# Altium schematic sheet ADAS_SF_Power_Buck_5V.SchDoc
size 431 x 279 mm; Date: Not shown in title block; ApprovedBy: Not shown in title block; CheckedBy: Not shown in title block; Author: Not shown in title block; CompanyName: Not shown in title block; Engineer: Not shown in title block; Organization: Not shown in title block; Address1: Not shown in title block; Address2: Not shown in title block; Address3: Not shown in title block; Address4: Not shown in title block; DocumentNumber: 1; Revision: Use project parameter SCH_Rev; SheetNumber: 3; SheetTotal: 15; PageSetup: Record=PageOptions¦CenterHorizontal=True¦CenterVertical=True¦PrintScale=0.66¦XCorrection=1.00¦YCorrection=1.00¦PrintKind=0¦BorderSize=5000000¦LeftOffset=0¦BottomOffset=0¦Orientation=2¦PaperLength=1000¦PaperWidth=1000¦Scale=100¦PaperSource=15¦PrintQuality=600¦MediaType=1¦DitherType=10¦PrintScaleMode=1¦PaperKind=Letter
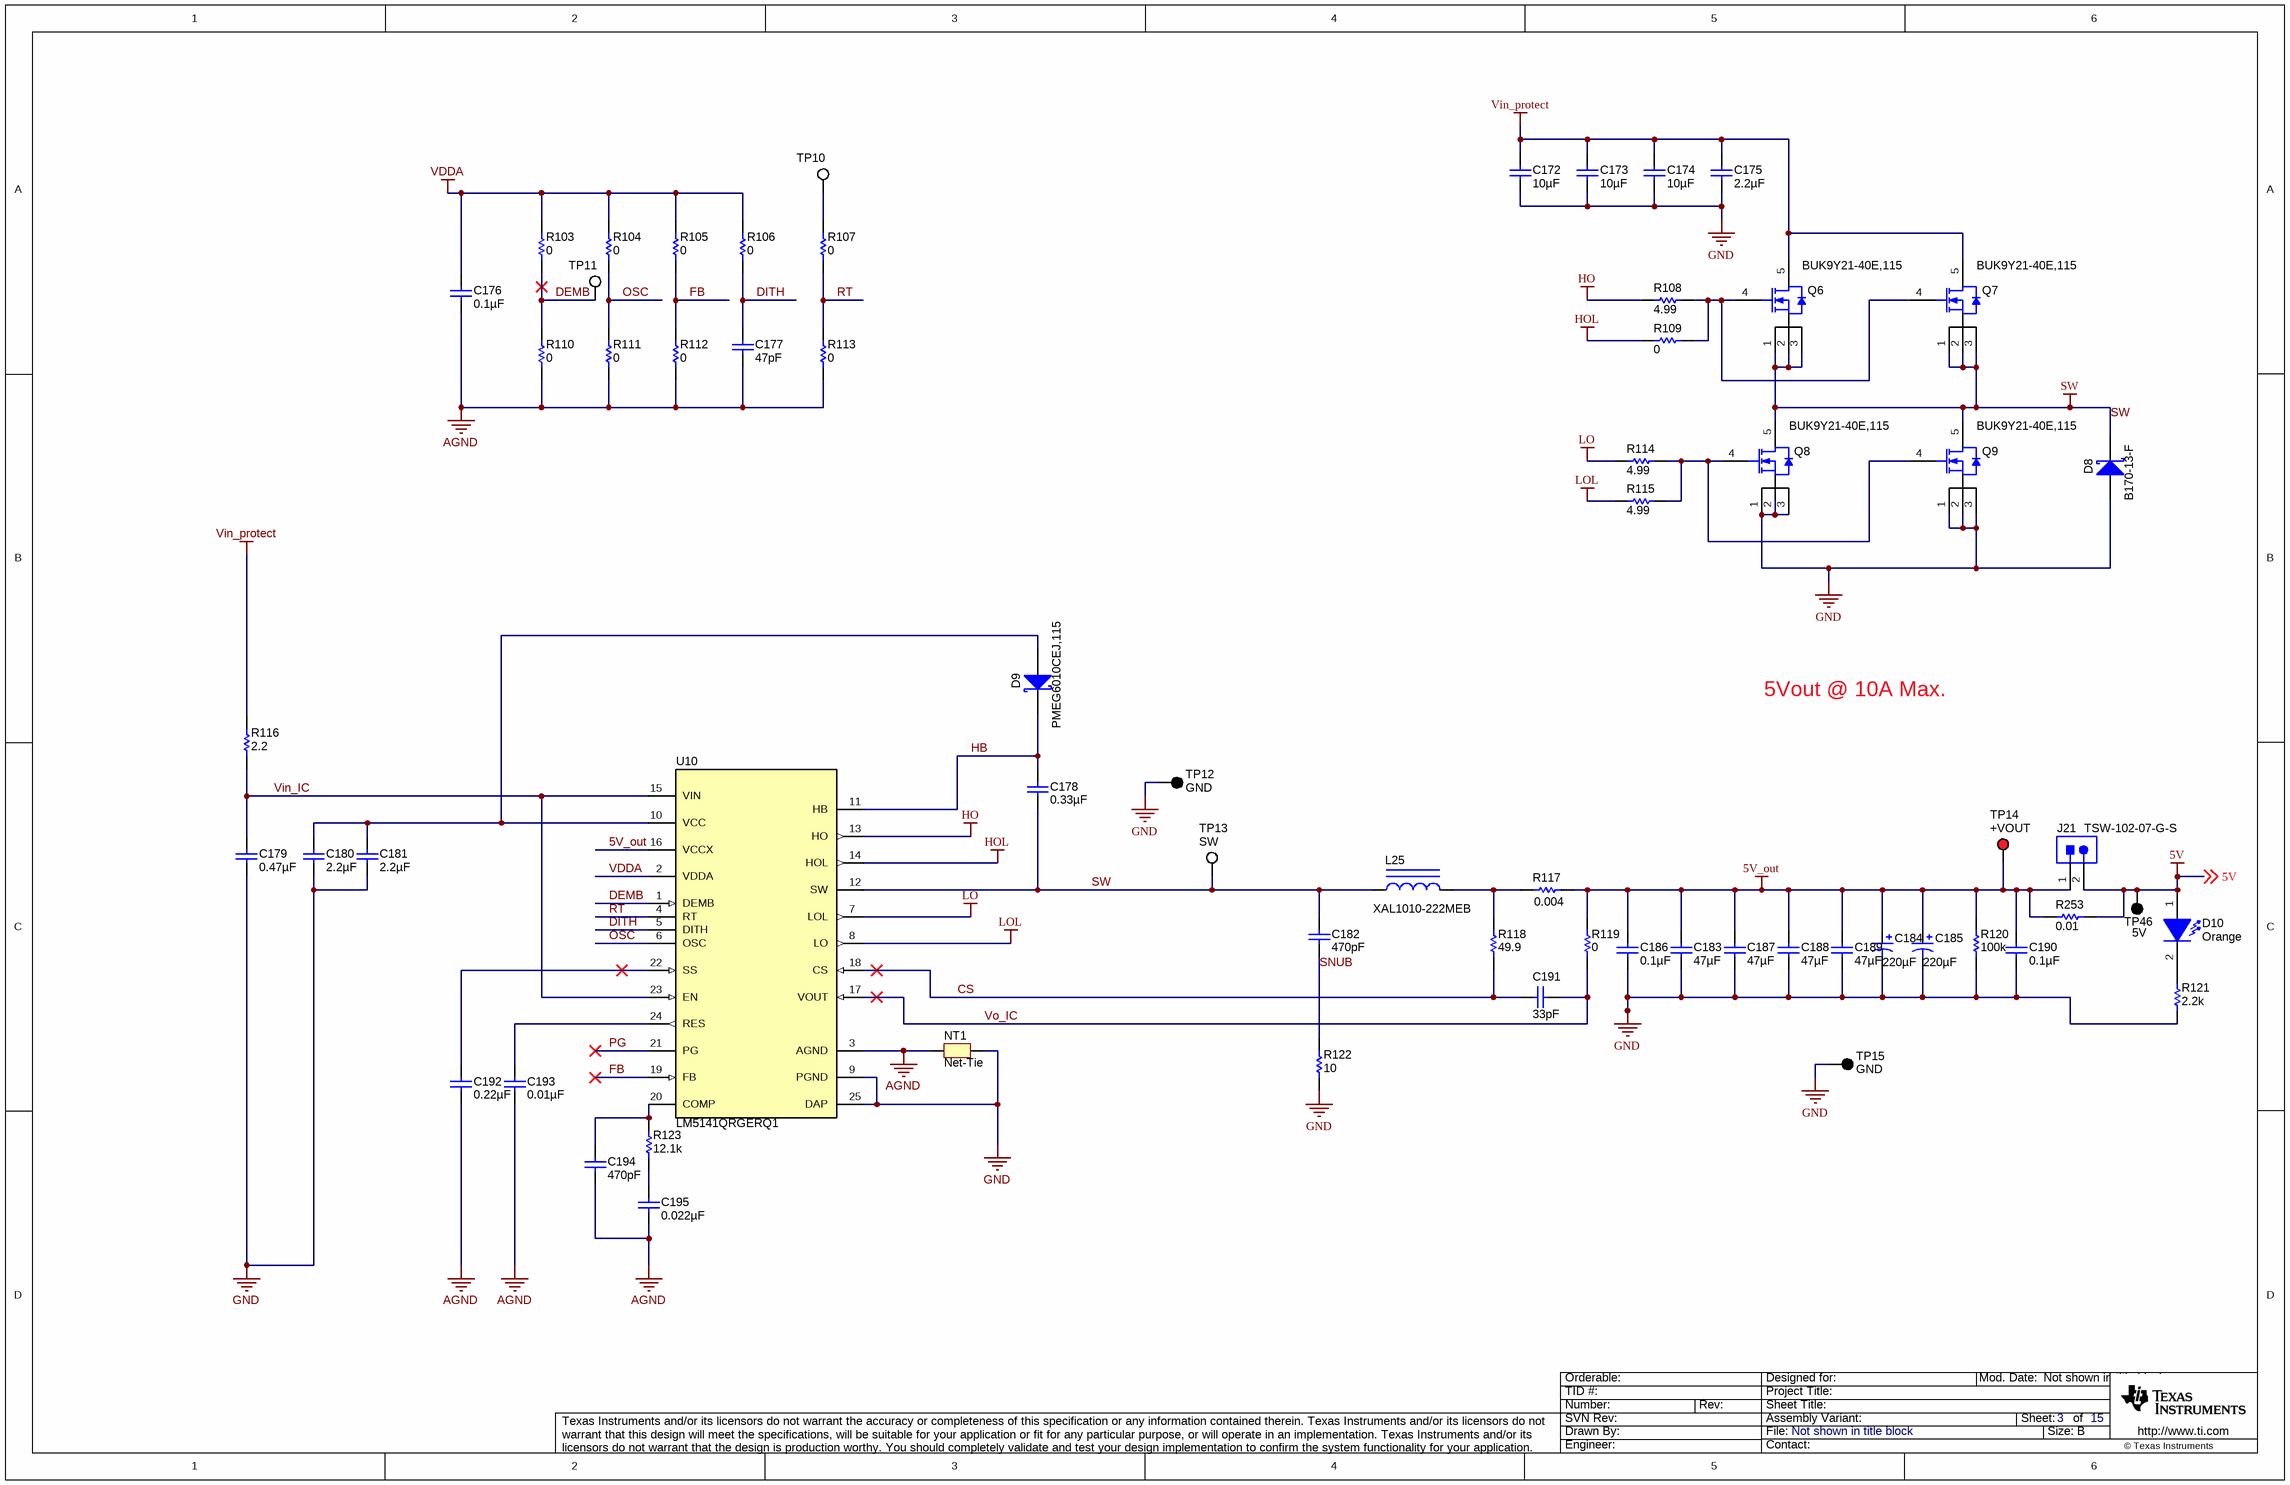
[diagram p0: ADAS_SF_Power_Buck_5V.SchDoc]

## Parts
C172  ValueDisplayed: 10µF  [1206_190]  (hidden comment: CGA5L3X5R1H106K160AB)
C173  ValueDisplayed: 10µF  [1206_190]  (hidden comment: CGA5L3X5R1H106K160AB)
C174  ValueDisplayed: 10µF  [1206_190]  (hidden comment: CGA5L3X5R1H106K160AB)
C175  2.2µF  [1206]
C176  ValueDisplayed: 0.1µF  [0402]  (hidden comment: GCM155R71H104KE02D)
C177  ValueDisplayed: 47pF  [0402]  (hidden comment: GRM1555C1E470JA01D)
C178  ValueDisplayed: 0.33µF  [0805_HV]  (hidden comment: GRM21AR72A334KAC5L)
C179  ValueDisplayed: 0.47µF  [0805_HV]  (hidden comment: GRM21BR72A474KA73L)
C180  ValueDisplayed: 2.2µF  [0603_HV]  (hidden comment: C0603C225M8PACTU)
C181  ValueDisplayed: 2.2µF  [0603_HV]  (hidden comment: C0603C225M8PACTU)
C182  ValueDisplayed: 470pF  [0805_HV]  (hidden comment: 08051A471JAT2A)
C183  ValueDisplayed: 47µF  [1206_180]  (hidden comment: GRM31CR61A476KE15L)
C184  ValueDisplayed: 220µF  [CAPSMT_62_H70]  (hidden comment: APXA6R3ARA221MH70G)
C185  ValueDisplayed: 220µF  [CAPSMT_62_H70]  (hidden comment: APXA6R3ARA221MH70G)
C186  ValueDisplayed: 0.1µF  [0603L]  (hidden comment: GRM188R72A104KA35D)
C187  ValueDisplayed: 47µF  [1206_180]  (hidden comment: GRM31CR61A476KE15L)
C188  ValueDisplayed: 47µF  [1206_180]  (hidden comment: GRM31CR61A476KE15L)
C189  ValueDisplayed: 47µF  [1206_180]  (hidden comment: GRM31CR61A476KE15L)
C190  ValueDisplayed: 0.1µF  [0603L]  (hidden comment: GRM188R72A104KA35D)
C191  ValueDisplayed: 33pF  [0603L]  (hidden comment: 06031A330JAT2A)
C192  ValueDisplayed: 0.22µF  [0402]  (hidden comment: GRM155R61A224KE19D)
C193  ValueDisplayed: 0.01µF  [0402]  (hidden comment: GCM155R71H103KA55D)
C194  ValueDisplayed: 470pF  [0402]  (hidden comment: GRM1555C1E471JA01D)
C195  ValueDisplayed: 0.022µF  [0402]  (hidden comment: GRM155R71C223KA01D)
D8  B170-13-F  [SMA]
D9  PMEG6010CEJ,115  [SOD-323F]
D10  value Orange  [LED_SMLP12_ORANGE]  (hidden comment: SML-P12DTT86)
J21  TSW-102-07-G-S  [TSW-102-07-G-S]
L25  XAL1010-222MEB  [XAL1010]
NT1  Net-Tie  [Net-Tie_10mil]  (net tie, no BOM)
Q6  BUK9Y21-40E,115  [LFPAK56]
Q7  BUK9Y21-40E,115  [LFPAK56]
Q8  BUK9Y21-40E,115  [LFPAK56]
Q9  BUK9Y21-40E,115  [LFPAK56]
R103  ValueDisplayed: 0  [0402]  (hidden comment: CRCW04020000Z0ED)
R104  ValueDisplayed: 0  [0402]  (hidden comment: CRCW04020000Z0ED)
R105  ValueDisplayed: 0  [0402]  (hidden comment: CRCW04020000Z0ED)
R106  ValueDisplayed: 0  [0402]  (hidden comment: CRCW04020000Z0ED)
R107  ValueDisplayed: 0  [0402]  (hidden comment: CRCW04020000Z0ED)
R108  ValueDisplayed: 4.99  [0603L]  (hidden comment: CRCW06034R99FKEA)
R109  ValueDisplayed: 0  [0603L]  (hidden comment: CRCW06030000Z0EA)
R110  ValueDisplayed: 0  [0402]  (hidden comment: CRCW04020000Z0ED)
R111  ValueDisplayed: 0  [0402]  (hidden comment: CRCW04020000Z0ED)
R112  ValueDisplayed: 0  [0402]  (hidden comment: CRCW04020000Z0ED)
R113  ValueDisplayed: 0  [0402]  (hidden comment: CRCW04020000Z0ED)
R114  ValueDisplayed: 4.99  [0603L]  (hidden comment: CRCW06034R99FKEA)
R115  ValueDisplayed: 4.99  [0603L]  (hidden comment: CRCW06034R99FKEA)
R116  ValueDisplayed: 2.2  [0603L]  (hidden comment: CRCW06032R20JNEA)
R117  value 0.004  [2010]  (hidden comment: PMR50HZPFV4L00)
R118  ValueDisplayed: 49.9  [0603L]  (hidden comment: CRCW060349R9FKEA)
R119  ValueDisplayed: 0  [0603L]  (hidden comment: CRCW06030000Z0EA)
R120  ValueDisplayed: 100k  [0805_HV]  (hidden comment: CRCW0805100KFKEA)
R121  ValueDisplayed: 2.2k  [0402]  (hidden comment: CRCW04022K20JNED)
R122  ValueDisplayed: 10  [2010]  (hidden comment: CRCW201010R0JNEF)
R123  ValueDisplayed: 12.1k  [0402]  (hidden comment: CRCW040212K1FKED)
R253  ValueDisplayed: 0.01  [KRL2012]  (hidden comment: KRL2012E-M-R010-F-T5)
TP10  5012  [Keystone5012]  (value not drawn)
TP11  5012  [Keystone5012]  (value not drawn)
TP12  GND  [Keystone5011]
TP13  SW  [Keystone5012]
TP14  +VOUT  [Keystone5010]
TP15  GND  [Keystone5011]
TP46  5V  [Keystone5011]
U10  LM5141QRGERQ1  [RGE0024J_NV]

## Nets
5V: D10.1(A) J21.2 R253.2 TP46.1 ; off-sheet 5V
5V_out: C183.1 C184.1(+) C185.1(+) C186.2 C187.1 C188.1 C189.1 C190.2 J21.1 R117.2 R119.2 R120.2 R253.1 TP14.1 U10.16(VCCX)
AGND: C176.2 C177.1 C192.2 C193.2 C194.1 C195.2 NT1.2 R110.1 R111.1 R112.1 R113.1 U10.3(AGND)
GND: C172.2 C173.2 C174.2 C175.2 C179.1 C180.2 C181.1 C183.2 C184.2(-) C185.2(-) C186.1 C187.2 C188.2 C189.2 C190.1 D8.2(A) NT1.1 Q8.1(S) Q8.2(S) Q8.3(S) Q9.1(S) Q9.2(S) Q9.3(S) R120.1 R121.2 R122.1 TP12.1 TP15.1 U10.9(PGND) U10.25(DAP)
HO: R108.1 U10.13(HO)
HOL: R109.1 U10.14(HOL)
LO: R114.1 U10.7(LOL)
LOL: R115.1 U10.8(LO)
SW: C178.1 C182.2 D8.1(K) L25.1 Q6.1(S) Q6.2(S) Q6.3(S) Q7.1(S) Q7.2(S) Q7.3(S) Q8.5(D) Q9.5(D) TP13.1 U10.12(SW)
VDDA: C176.1 R103.2 R104.2 R105.2 R106.2 U10.2(VDDA)
Vin_protect: C172.1 C173.1 C174.1 C175.1 Q6.5(D) Q7.5(D) R116.2
CS: C191.2 R118.1 U10.18(CS)
DEMB: R103.1 R110.2 TP11.1 U10.1(DEMB)
DITH: C177.2 R106.1 U10.5(DITH)
FB: R105.1 R112.2 U10.19(FB)
HB: C178.2 D9.1(K) U10.11(HB)
OSC: R104.1 R111.2 U10.6(OSC)
PG: U10.21(PG)
RT: R107.1 R113.2 U10.4(RT)
SNUB: C182.1 R122.2
Vin_IC: C179.2 R116.1 U10.15(VIN) U10.23(EN)
Vo_IC: C191.1 R119.1 U10.17(VOUT)
NetC180_1: C180.1 C181.2 D9.2(A) U10.10(VCC)
NetC192_1: C192.1 U10.22(SS)
NetC193_1: C193.1 U10.24(RES)
NetC194_2: C194.2 R123.2 U10.20(COMP)
NetC195_1: C195.1 R123.1
NetD10_2: D10.2(K) R121.1
NetL25_2: L25.2 R117.1 R118.2
NetQ6_4: Q6.4(G) Q7.4(G) R108.2 R109.2
NetQ8_4: Q8.4(G) Q9.4(G) R114.2 R115.2
NetR107_2: R107.2 TP10.1

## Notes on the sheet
- 5Vout @ 10A Max.

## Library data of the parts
C172-C174 = CGA5L3X5R1H106K160AB: CAP, CERM, 10 µF, 50 V, +/- 10%, X5R, 1206_190; Manufacturer: TDK; Polarized: N; CompType: Capacitor; Value: 10uF; U/M: EA; Cap_F: 0.00001; Tolerance_%: 10; Value1: Unknown; VDC_V: 50; Value2: 50V; TaMin_C: -55; TaMax_C: 85; Cap_Case: 1206
C175 = CL31B225KCHSNNE: CAP CER 2.2UF 100V 10% X7R 1206; Manufacturer: Samsung Electro-Mechanics America, Inc; SymbolVersion: use current date i.e. 2008-05-20; SymbolCreator: Use a-id; CompType: Used in some BOM reports.  Useful for finding later.; U/M: EA, IN, or GM
C176 = GCM155R71H104KE02D: CAP, CERM, 0.1 µF, 50 V, +/- 10%, X7R, AEC-Q200 Grade 1, 0402; Manufacturer: MuRata; Polarized: N; CompType: Capacitor; Value: 0.1uF; U/M: EA; Cap_F: 0.0000001; Tolerance_%: 10; Value1: Unknown; VDC_V: 50; Value2: 50V; TaMin_C: -55; TaMax_C: 125; AEC Category: Q200; AEC Qualified: Y; AEC Grade: 1; SizeArea_mm2: 0.5; SizeAreaWB_mm2: 3; SizeZ_mm: 0.6
C177 = GRM1555C1E470JA01D: CAP, CERM, 47 pF, 25 V, +/- 5%, C0G/NP0, 0402; Manufacturer: MuRata; Polarized: N; CompType: Capacitor; Value: 47pF; U/M: EA; Cap_F: 0.000000000047; Tolerance_%: 5; Value1: Unknown; VDC_V: 25; Value2: 25V; TaMin_C: -55; TaMax_C: 125; AEC Category: Q200
C178 = GRM21AR72A334KAC5L: CAP, CERM, 0.33 µF, 100 V, +/- 10%, X7R, 0805; Manufacturer: MuRata; Polarized: N; CompType: Capacitor; Value: 0.33uF; U/M: EA; Cap_F: 0.00000033; Tolerance_%: 10; Value1: Unknown; VDC_V: 100; Value2: 100V; TaMin_C: -55; TaMax_C: 125; Cap_Case: 0805
C179 = GRM21BR72A474KA73L: CAP, CERM, 0.47uF, 100V, +/-10%, X7R, 0805; Manufacturer: MuRata; Polarized: N; CompType: Capacitor; U/M: EA; Cap_F: 0.00000047; Tolerance_%: 10; Value1: Unknown; VDC_V: 100; TaMin_C: -55; TaMax_C: 125; Cap_Case: 0805
C180 C181 = C0603C225M8PACTU: CAP, CERM, 2.2 µF, 10 V, +/- 20%, X5R, 0603; Manufacturer: Kemet; Polarized: N; CompType: Capacitor; Value: 2.2uF; U/M: EA; Cap_F: 0.0000022; Tolerance_%: 20; Value1: Unknown; VDC_V: 10; Value2: 10V; TaMin_C: -55; TaMax_C: 85; Cap_Case: 0603
C182 = 08051A471JAT2A: CAP, CERM, 470 pF, 100 V, +/- 5%, C0G/NP0, 0805; Manufacturer: AVX; Polarized: N; CompType: Capacitor; Value: 470pF; U/M: EA; Cap_F: 0.00000000047; Tolerance_%: 5; ESR_ohm: 0.159; Value1: 0.159 ohm; VDC_V: 100; Value2: 100V; TaMin_C: -55; TaMax_C: 125; Cap_Case: 0805; SizeArea_mm2: 2.5; SizeAreaWB_mm2: 6.75; SizeX_mm: 2; SizeY_mm: 1.25; SizeZ_mm: 1.45; AEC Category: Q200
C183 C187-C189 = GRM31CR61A476KE15L: CAP, CERM, 47 µF, 10 V, +/- 10%, X5R, 1206; Manufacturer: MuRata; Polarized: N; CompType: Capacitor; Value: 47uF; U/M: EA; Cap_F: 0.000047; Tolerance_%: 10; Value1: Unknown; Value2: 10V; TaMin_C: -55; TaMax_C: 85; Cap_Case: 1206; SizeArea_mm2: 5.12; SizeAreaWB_mm2: 10.92; SizeX_mm: 3.2; SizeY_mm: 1.6; SizeZ_mm: 1.8; AEC Category: Q200
C184 C185 = APXA6R3ARA221MH70G: CAP, AL, 220 µF, 6.3 V, +/- 20%, 0.025 ohm, SMD; Manufacturer: Chemi-Con; Polarized: Y; CompType: Capacitor; Value: 220uF; U/M: EA; Cap_F: 0.00022; Tolerance_%: 20; VDC_V: 6.3; Value2: 6.3V; ESR_ohm: 0.025; IRMS_A: 3.02; TaMin_C: -55; TaMax_C: 105; Cap_Case: H70
C186 C190 = GRM188R72A104KA35D: CAP, CERM, 0.1uF, 100V, +/-10%, X7R, 0603; Manufacturer: MuRata; Polarized: N; CompType: Capacitor; U/M: EA; Cap_F: 0.0000001; Tolerance_%: 10; Value1: Unknown; VDC_V: 100; TaMin_C: -55; TaMax_C: 125; Cap_Case: 0603
C191 = 06031A330JAT2A: CAP, CERM, 33 pF, 100 V, +/- 5%, C0G/NP0, 0603; Manufacturer: AVX; Polarized: N; CompType: Capacitor; Value: 33pF; U/M: EA; Cap_F: 0.000000000033; Tolerance_%: 5; ESR_ohm: 0.209; Value1: 0.209 ohm; VDC_V: 100; Value2: 100V; TaMin_C: -55; TaMax_C: 125; Cap_Case: 0603
C192 = GRM155R61A224KE19D: CAP, CERM, 0.22 µF, 10 V, +/- 10%, X5R, 0402; Manufacturer: MuRata; Polarized: N; CompType: Capacitor; Value: 0.22uF; U/M: EA; Cap_F: 0.00000022; Tolerance_%: 10; Value1: Unknown; Value2: 10V; TaMin_C: -55; TaMax_C: 85; SizeArea_mm2: 0.5; SizeAreaWB_mm2: 3; SizeX_mm: 1; SizeZ_mm: 0.6; AEC Category: Q200
C193 = GCM155R71H103KA55D: CAP, CERM, 0.01uF, 50V, +/-10%, C0G/NP0, 0402; Manufacturer: MuRata; Polarized: N; CompType: Capacitor; U/M: EA; Cap_F: 0.00000001; Tolerance_%: 10; Value1: Unknown; VDC_V: 50; TaMin_C: -55; TaMax_C: 125
C194 = GRM1555C1E471JA01D: CAP, CERM, 470 pF, 25 V, +/- 5%, C0G/NP0, 0402; Manufacturer: MuRata; Polarized: N; CompType: Capacitor; Value: 470pF; U/M: EA; Cap_F: 0.00000000047; Tolerance_%: 5; Value1: Unknown; VDC_V: 25; Value2: 25V; TaMin_C: -55; TaMax_C: 125; SizeArea_mm2: 0.5; SizeAreaWB_mm2: 3; SizeX_mm: 1; SizeZ_mm: 0.6; AEC Category: Q200
C195 = GRM155R71C223KA01D: CAP, CERM, 0.022 µF, 16 V, +/- 10%, X7R, 0402; Manufacturer: MuRata; Polarized: N; CompType: Capacitor; Value: 0.022uF; U/M: EA; Cap_F: 0.000000022; Tolerance_%: 10; Value1: Unknown; VDC_V: 16; Value2: 16V; TaMin_C: -55; TaMax_C: 125; SizeArea_mm2: 0.5; SizeAreaWB_mm2: 3; SizeX_mm: 1; SizeZ_mm: 0.6; AEC Category: Q200
D8 = B170-13-F: Diode, Schottky, 70V, 1A, SMA; Manufacturer: Diodes Inc.; U/M: EA; Vr_V: 70; Io_A: 1; Vf_V: 0.79; Value2: 0.79V; TJmax_C: 150; RJC_CperW: 25
D9 = PMEG6010CEJ,115: Diode, Schottky, 60 V, 1 A, SOD-323F; Manufacturer: NXP Semiconductor; U/M: EA; Vf_V: 0.66; Value: 60V; Value1: 1A; Value2: 0.66V; Io_A: 1; Vr_V: 60; TJmax_C: 150
D10 = SML-P12DTT86: LED, Orange, SMD; Manufacturer: Rohm; Type: InGaN; Vf_V: 2.1; Value2: 2.1V; Io_A: 0.02; Tjmax_C: 85; Value1: W; U/M: EA
J21 = TSW-102-07-G-S: Header, 100mil, 2x1, Gold, TH; Manufacturer: Samtec; SymbolCreator: a0412235; Pitch_mm: 2.54; Gender: Male; Shrouded: N; Row_Count: 1; Current_A: 6.3; Voltage_V: 550; Cert_CSA: Y
L25 = XAL1010-222MEB: Inductor, Shielded, Composite, 2.2 µH, 32 A, 0.00255 ohm, SMD; Manufacturer: Coilcraft; Value: 2.2uH; Ind_H: 2.2E-6; ValueDisplayed: 2.2µH; Imax_A: 32; Irms: 32A @ 40C rise; Isat: 34A @ 30% inductance drop; Value2: 32A
NT1 = Net-Tie: Single point connection between nets.; SymbolCreator: codlsc
Q6-Q9 = BUK9Y21-40E,115: MOSFET, N-CH, 40 V, 33 A, AEC-Q101, SOT669; Manufacturer: NXP Semiconductor; Alternate Manufacturer: None; SymbolCreator: a0412235; U/M: EA; ChType: N; Value: 40V; VdsMax_V: 40; Value1: ? ohm; Value2: 7 nC; QgTyp_nC: 7; Vgs_V: 10; IdsMax_A: 33; AEC Category: Q101; AEC Qualified: Y
R103-R107 R110-R113 = CRCW04020000Z0ED: RES, 0, 5%, 0.063 W, 0402; Manufacturer: Vishay-Dale; CompType: Resistor; Value: 0; Value_Code: 0000; Tolerance_%: 5; Power_W: 0.063; Value2: 0.063W; VDC_V: 50; TempCo: 200 ppm/C; EIA_Code: E24; U/M: EA; AEC Category: Q200
R108 R114 R115 = CRCW06034R99FKEA: RES, 4.99, 1%, 0.1 W, 0603; Manufacturer: Vishay-Dale; CompType: Resistor; Value: 4.99; Value_Code: 4R99; Tolerance_%: 1; Power_W: 0.1; Value2: 0.1W; VDC_V: 75; TempCo: 100 ppm/C; EIA_Code: E96; U/M: EA
R109 R119 = CRCW06030000Z0EA: RES, 0, 5%, 0.1 W, 0603; Manufacturer: Vishay-Dale; CompType: Resistor; Value: 0; Value_Code: 0000; Tolerance_%: 5; Power_W: 0.1; Value2: 0.1W; VDC_V: 75; TempCo: 200 ppm/C; EIA_Code: E24; U/M: EA
R116 = CRCW06032R20JNEA: RES, 2.2, 5%, 0.1 W, 0603; Manufacturer: Vishay-Dale; CompType: Resistor; Value: 2.2; Value_Code: 2R20; Tolerance_%: 5; Power_W: 0.1; Value2: 0.1W; VDC_V: 75; TempCo: 200 ppm/C; EIA_Code: E24; U/M: EA
R117 = Resistor: RES, 0.004 ohm, 1%, 1W, 2010, AEC-Q200 Qualified; Manufacturer: Rohm Semiconductor; U/M: EA
R118 = CRCW060349R9FKEA: RES, 49.9, 1%, 0.1 W, 0603; Manufacturer: Vishay-Dale; CompType: Resistor; Value: 49.9; Value_Code: 49R9; Tolerance_%: 1; Power_W: 0.1; Value2: 0.1W; VDC_V: 75; TempCo: 100 ppm/C; EIA_Code: E96; U/M: EA
R120 = CRCW0805100KFKEA: RES, 100 k, 1%, 0.125 W, 0805; Manufacturer: Vishay-Dale; CompType: Resistor; Value: 100k; Res_ohm: 100000; Tolerance_%: 1; Power_W: 0.125; Value2: 0.125W; VDC_V: 150; TempCo: 100 ppm/C; EIA_Code: E96; U/M: EA
R121 = CRCW04022K20JNED: RES, 2.2 k, 5%, 0.063 W, 0402; Manufacturer: Vishay-Dale; CompType: Resistor; Value: 2.2k; Res_ohm: 2200; Value_Code: 2k20; Tolerance_%: 5; Power_W: 0.063; Value2: 0.063W; VDC_V: 50; TempCo: 200 ppm/C; EIA_Code: E24; U/M: EA
R122 = CRCW201010R0JNEF: RES, 10, 5%, 0.75 W, 2010; Manufacturer: Vishay-Dale; CompType: Resistor; Value: 10; Value_Code: 10R0; Tolerance_%: 5; Power_W: 0.75; Value2: 0.75W; VDC_V: 400; TempCo: 200 ppm/C; EIA_Code: E24; U/M: EA
R123 = CRCW040212K1FKED: RES, 12.1 k, 1%, 0.063 W, 0402; Manufacturer: Vishay-Dale; CompType: Resistor; Value: 12.1k; Res_ohm: 12100; Value_Code: 12k1; Tolerance_%: 1; Power_W: 0.063; Value2: 0.063W; VDC_V: 50; TempCo: 100 ppm/C; SizeArea_mm2: 0.5; SizeZ_mm: 0.6; EIA_Code: E96; U/M: EA; AEC Category: Q200
R253 = KRL2012E-M-R010-F-T5: RES, 0.01, 1%, 1 W, AEC-Q200 Grade 0, 0508; Manufacturer: Susumu Co Ltd; CompType: Resistor; Value: 0.01; Value_Code: R010; Tolerance_%: 1; Value2: 1W; TempCo: 25 ppm/C; EIA_Code: E96; U/M: EA; AEC Category: Q200; AEC Qualified: Y; AEC Grade: 0
TP10 TP11 = 5012: Test Point, Multipurpose, White, TH; Manufacturer: Keystone; CompType: Test Point Loop; ContactFinish: Silver
TP12 TP15 TP46 = 5011: Test Point, Multipurpose, Black, TH; Manufacturer: Keystone; CompType: Test Point Loop; U/M: EA
TP13 = 5012: Test Point, Multipurpose, White, TH; Manufacturer: Keystone; CompType: Test Point Loop; U/M: EA
TP14 = 5010: Test Point, Multipurpose, Red, TH; Manufacturer: Keystone; CompType: Test Point Loop; U/M: EA
U10 = CMP-0076290-1: Wide Input 2.2MHz low Iq Synchronous Buck Controller, RGE0024J (VQFN-24); Alternate Manufacturer: Texas Instruments; SizeX_mm: 4.0; CompType: IC; SizeAreaWB_mm2: 25.0; SizeZ_mm: 1.0; U/M: EA; SizeArea_mm2: 16.0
